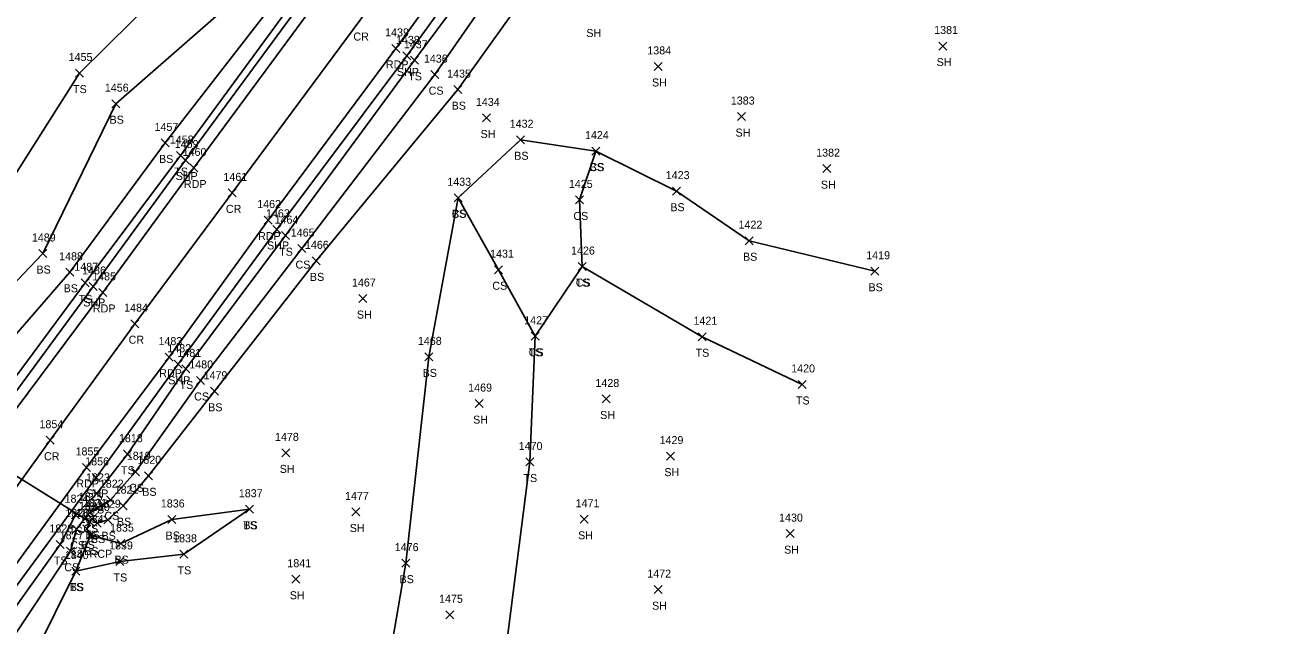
# Model space of a CAD drawing. Extents: x 1520648 to 1523413, y 732854 to 735518.
# Drawn here: x 1522390.5 to 1522704.9, y 734102.2 to 734252.2 of the extents above; entities that cross this region are included whole.
import ezdxf

# ---------------------------------------------------------------- set-up
doc = ezdxf.new("R2010")
doc.units = 0
for name, color, linetype in [('D_A', 7, 'Continuous'), ('D_C', 7, 'Continuous'), ('D_I', 7, 'Continuous'), ('D_TIC', 7, 'Continuous'), ('DCP', 7, 'Continuous'), ('L_A', 7, 'Continuous'), ('L_I', 7, 'Continuous'), ('L_TIC', 7, 'Continuous'), ('LELB', 7, 'Continuous'), ('P_A', 7, 'Continuous'), ('P_I', 7, 'Continuous'), ('P_TIC', 7, 'Continuous'), ('PET', 7, 'Continuous'), ('PRC', 7, 'Continuous'), ('PSP', 7, 'Continuous')]:
    doc.layers.add(name, color=color, linetype=linetype)

msp = doc.modelspace()

# ---------------------------------------------------------------- linework, layer by layer
at = {"layer": 'D_TIC'}
for points in [[(1522405.62, 734127.21), (1522407.62, 734129.21)], [(1522407.62, 734127.21), (1522405.62, 734129.21)]]:
    msp.add_lwpolyline(points, dxfattribs=at)
at = {"layer": 'DCP'}
msp.add_lwpolyline([(1522367.37, 734152.56), (1522406.62, 734128.21)], dxfattribs=at)
at = {"layer": 'L_TIC'}
for points in [[(1522618.68, 734245.97), (1522620.68, 734247.97)], [(1522620.68, 734245.97), (1522618.68, 734247.97)], [(1522486.75, 734242.4), (1522488.75, 734244.4)], [(1522488.75, 734242.4), (1522486.75, 734244.4)], [(1522547.57, 734240.87), (1522549.57, 734242.87)], [(1522549.57, 734240.87), (1522547.57, 734242.87)], [(1522403.02, 734239.22), (1522405.02, 734241.22)], [(1522405.02, 734239.22), (1522403.02, 734241.22)], [(1522491.81, 734238.83), (1522493.81, 734240.83)], [(1522493.81, 734238.83), (1522491.81, 734240.83)], [(1522497.57, 734235.08), (1522499.57, 734237.08)], [(1522499.57, 734235.08), (1522497.57, 734237.08)], [(1522412.12, 734231.57), (1522414.12, 734233.57)], [(1522414.12, 734231.57), (1522412.12, 734233.57)], [(1522504.75, 734228.01), (1522506.75, 734230.01)], [(1522506.75, 734228.01), (1522504.75, 734230.01)], [(1522568.44, 734228.36), (1522570.44, 734230.36)], [(1522570.44, 734228.36), (1522568.44, 734230.36)], [(1522424.47, 734221.78), (1522426.47, 734223.78)], [(1522426.47, 734221.78), (1522424.47, 734223.78)], [(1522513.21, 734222.57), (1522515.21, 734224.57)], [(1522515.21, 734222.57), (1522513.21, 734224.57)], [(1522428.3, 734218.62), (1522430.3, 734220.62)], [(1522430.3, 734218.62), (1522428.3, 734220.62)], [(1522532.01, 734219.74), (1522534.01, 734221.74)], [(1522534.01, 734219.74), (1522532.01, 734221.74)], [(1522532.01, 734219.74), (1522534.01, 734221.74)], [(1522534.01, 734219.74), (1522532.01, 734221.74)], [(1522589.77, 734215.36), (1522591.77, 734217.36)], [(1522591.77, 734215.36), (1522589.77, 734217.36)], [(1522552.2, 734209.74), (1522554.2, 734211.74)], [(1522554.2, 734209.74), (1522552.2, 734211.74)], [(1522497.61, 734208.08), (1522499.61, 734210.08)], [(1522499.61, 734208.08), (1522497.61, 734210.08)], [(1522497.61, 734208.08), (1522499.61, 734210.08)], [(1522499.61, 734208.08), (1522497.61, 734210.08)], [(1522527.98, 734207.55), (1522529.98, 734209.55)], [(1522529.98, 734207.55), (1522527.98, 734209.55)], [(1522454.5, 734198.63), (1522456.5, 734200.63)], [(1522456.5, 734198.63), (1522454.5, 734200.63)], [(1522570.36, 734197.37), (1522572.36, 734199.37)], [(1522572.36, 734197.37), (1522570.36, 734199.37)], [(1522393.84, 734194.17), (1522395.84, 734196.17)], [(1522395.84, 734194.17), (1522393.84, 734196.17)], [(1522458.56, 734195.4), (1522460.56, 734197.4)], [(1522460.56, 734195.4), (1522458.56, 734197.4)], [(1522462.16, 734192.34), (1522464.16, 734194.34)], [(1522464.16, 734192.34), (1522462.16, 734194.34)], [(1522507.73, 734190.13), (1522509.73, 734192.13)], [(1522509.73, 734190.13), (1522507.73, 734192.13)], [(1522528.58, 734190.91), (1522530.58, 734192.91)], [(1522530.58, 734190.91), (1522528.58, 734192.91)], [(1522528.58, 734190.91), (1522530.58, 734192.91)], [(1522530.58, 734190.91), (1522528.58, 734192.91)], [(1522400.64, 734189.49), (1522402.64, 734191.49)], [(1522402.64, 734189.49), (1522400.64, 734191.49)], [(1522404.44, 734186.85), (1522406.44, 734188.85)], [(1522406.44, 734186.85), (1522404.44, 734188.85)], [(1522601.7, 734189.74), (1522603.7, 734191.74)], [(1522603.7, 734189.74), (1522601.7, 734191.74)], [(1522473.84, 734182.93), (1522475.84, 734184.93)], [(1522475.84, 734182.93), (1522473.84, 734184.93)], [(1522516.84, 734173.51), (1522518.84, 734175.51)], [(1522518.84, 734173.51), (1522516.84, 734175.51)], [(1522516.84, 734173.51), (1522518.84, 734175.51)], [(1522518.84, 734173.51), (1522516.84, 734175.51)], [(1522558.55, 734173.4), (1522560.55, 734175.4)], [(1522560.55, 734173.4), (1522558.55, 734175.4)], [(1522490.31, 734168.37), (1522492.31, 734170.37)], [(1522492.31, 734168.37), (1522490.31, 734170.37)], [(1522429.63, 734165.37), (1522431.63, 734167.37)], [(1522431.63, 734165.37), (1522429.63, 734167.37)], [(1522433.24, 734162.49), (1522435.24, 734164.49)], [(1522435.24, 734162.49), (1522433.24, 734164.49)], [(1522436.74, 734159.79), (1522438.74, 734161.79)], [(1522438.74, 734159.79), (1522436.74, 734161.79)], [(1522583.61, 734161.49), (1522585.61, 734163.49)], [(1522585.61, 734161.49), (1522583.61, 734163.49)], [(1522502.89, 734156.71), (1522504.89, 734158.71)], [(1522504.89, 734156.71), (1522502.89, 734158.71)], [(1522534.62, 734157.86), (1522536.62, 734159.86)], [(1522536.62, 734157.86), (1522534.62, 734159.86)], [(1522415.02, 734144.08), (1522417.02, 734146.08)], [(1522417.02, 734144.08), (1522415.02, 734146.08)], [(1522454.56, 734144.41), (1522456.56, 734146.41)], [(1522456.56, 734144.41), (1522454.56, 734146.41)], [(1522550.65, 734143.6), (1522552.65, 734145.6)], [(1522552.65, 734143.6), (1522550.65, 734145.6)], [(1522416.99, 734139.69), (1522418.99, 734141.69)], [(1522418.99, 734139.69), (1522416.99, 734141.69)], [(1522515.54, 734142.14), (1522517.54, 734144.14)], [(1522517.54, 734142.14), (1522515.54, 734144.14)], [(1522420.27, 734138.69), (1522422.27, 734140.69)], [(1522422.27, 734138.69), (1522420.27, 734140.69)], [(1522407.37, 734134.28), (1522409.37, 734136.28)], [(1522409.37, 734134.28), (1522407.37, 734136.28)], [(1522410.81, 734132.72), (1522412.81, 734134.72)], [(1522412.81, 734132.72), (1522410.81, 734134.72)], [(1522413.94, 734131.23), (1522415.94, 734133.23)], [(1522415.94, 734131.23), (1522413.94, 734133.23)], [(1522445.53, 734130.34), (1522447.53, 734132.34)], [(1522447.53, 734130.34), (1522445.53, 734132.34)], [(1522445.53, 734130.34), (1522447.53, 734132.34)], [(1522447.53, 734130.34), (1522445.53, 734132.34)], [(1522402.01, 734128.97), (1522404.01, 734130.97)], [(1522404.01, 734128.97), (1522402.01, 734130.97)], [(1522405.56, 734129.49), (1522407.56, 734131.49)], [(1522407.56, 734129.49), (1522405.56, 734131.49)], [(1522406.08, 734127.93), (1522408.08, 734129.93)], [(1522408.08, 734127.93), (1522406.08, 734129.93)], [(1522410.1, 734127.72), (1522412.1, 734129.72)], [(1522412.1, 734127.72), (1522410.1, 734129.72)], [(1522426.11, 734127.78), (1522428.11, 734129.78)], [(1522428.11, 734127.78), (1522426.11, 734129.78)], [(1522472.06, 734129.66), (1522474.06, 734131.66)], [(1522474.06, 734129.66), (1522472.06, 734131.66)], [(1522529.11, 734127.84), (1522531.11, 734129.84)], [(1522531.11, 734127.84), (1522529.11, 734129.84)], [(1522402.25, 734125.38), (1522404.25, 734127.38)], [(1522404.25, 734125.38), (1522402.25, 734127.38)], [(1522404.88, 734125.45), (1522406.88, 734127.45)], [(1522406.88, 734125.45), (1522404.88, 734127.45)], [(1522405.78, 734123.9), (1522407.78, 734125.9)], [(1522407.78, 734123.9), (1522405.78, 734125.9)], [(1522405.78, 734123.9), (1522407.78, 734125.9)], [(1522407.78, 734123.9), (1522405.78, 734125.9)], [(1522407.44, 734126.9), (1522409.44, 734128.9)], [(1522409.44, 734126.9), (1522407.44, 734128.9)], [(1522580.58, 734124.25), (1522582.58, 734126.25)], [(1522582.58, 734124.25), (1522580.58, 734126.25)], [(1522398.21, 734121.54), (1522400.21, 734123.54)], [(1522400.21, 734121.54), (1522398.21, 734123.54)], [(1522413.36, 734121.75), (1522415.36, 734123.75)], [(1522415.36, 734121.75), (1522413.36, 734123.75)], [(1522400.8, 734119.85), (1522402.8, 734121.85)], [(1522402.8, 734119.85), (1522400.8, 734121.85)], [(1522429.11, 734119.09), (1522431.11, 734121.09)], [(1522431.11, 734119.09), (1522429.11, 734121.09)], [(1522402.15, 734114.91), (1522404.15, 734116.91)], [(1522404.15, 734114.91), (1522402.15, 734116.91)], [(1522402.15, 734114.91), (1522404.15, 734116.91)], [(1522404.15, 734114.91), (1522402.15, 734116.91)], [(1522413.13, 734117.31), (1522415.13, 734119.31)], [(1522415.13, 734117.31), (1522413.13, 734119.31)], [(1522484.55, 734116.88), (1522486.55, 734118.88)], [(1522486.55, 734116.88), (1522484.55, 734118.88)], [(1522457.09, 734112.87), (1522459.09, 734114.87)], [(1522459.09, 734112.87), (1522457.09, 734114.87)], [(1522547.58, 734110.27), (1522549.58, 734112.27)], [(1522549.58, 734110.27), (1522547.58, 734112.27)], [(1522495.55, 734103.98), (1522497.55, 734105.98)], [(1522497.55, 734103.98), (1522495.55, 734105.98)]]:
    msp.add_lwpolyline(points, dxfattribs=at)
at = {"layer": 'LELB'}
for points in [[(1522785.93, 734645.15), (1522756.48, 734606.7), (1522726.02, 734567.19), (1522697.44, 734525.1), (1522656.53, 734469.54), (1522622.12, 734421.12), (1522590.47, 734378.52), (1522566.34, 734346.2), (1522539.5, 734310.16), (1522511.43, 734266.75), (1522492.81, 734239.83), (1522459.56, 734196.4), (1522434.24, 734163.49), (1522417.99, 734140.69), (1522411.81, 734133.72), (1522406.56, 734130.49), (1522403.25, 734126.38), (1522401.8, 734120.85), (1522386.75, 734098.22)], [(1522693.92, 734527.21), (1522653.61, 734471.8), (1522618.94, 734423.11), (1522588.19, 734381.05), (1522564.23, 734347.84), (1522537.14, 734311.9), (1522506.92, 734269.19), (1522487.75, 734243.4), (1522455.5, 734199.63), (1522430.63, 734166.37), (1522416.02, 734145.08), (1522408.37, 734135.28), (1522403.01, 734129.97), (1522399.21, 734122.54), (1522383.71, 734100.99)], [(1522704.24, 734521.86), (1522660.18, 734466.65), (1522629.05, 734416.78), (1522593.47, 734376.61), (1522578.57, 734355.18), (1522577.23, 734351.34), (1522574.67, 734346.79), (1522570.51, 734341.94), (1522542.46, 734307.95), (1522517.77, 734263), (1522498.57, 734236.08), (1522463.16, 734193.34), (1522437.74, 734160.79), (1522421.27, 734139.69), (1522414.94, 734132.23), (1522411.1, 734128.72), (1522408.44, 734127.9), (1522407.08, 734128.93), (1522405.88, 734126.45), (1522406.78, 734124.9), (1522403.15, 734115.91), (1522392.7, 734094.89), (1522365.31, 734053.94)], [(1522395.09, 734350.53), (1522415.25, 734331.59), (1522444.22, 734311.43), (1522451.41, 734298.65), (1522468.17, 734280.37), (1522463.01, 734272.97), (1522457.88, 734264.64), (1522425.47, 734222.78), (1522401.64, 734190.49), (1522371.91, 734156.31), (1522371.61, 734153.22)], [(1522384.49, 734338.49), (1522408.87, 734322.63), (1522444.22, 734311.43), (1522437.11, 734272.85), (1522404.02, 734240.22), (1522381.49, 734204.71), (1522358.63, 734188.03), (1522348.69, 734185.07), (1522337.79, 734178.25), (1522344.61, 734158.44), (1522355.97, 734160.39), (1522362.76, 734161.47), (1522371.91, 734156.31), (1522376.81, 734157.78), (1522380.78, 734154.69)], [(1522457.97, 734316.51), (1522465.36, 734303.49), (1522470.91, 734292.36), (1522471.73, 734284.06), (1522466.06, 734271.74), (1522460.87, 734262.7), (1522429.3, 734219.62), (1522405.44, 734187.85), (1522380.78, 734154.69), (1522358.58, 734123.49), (1522334.87, 734095.05), (1522309.58, 734064.85), (1522289.9, 734038.9), (1522256.58, 733995.71), (1522247.93, 733981.24), (1522246.39, 733977.74)], [(1522468.17, 734280.37), (1522452.7, 734267.12), (1522413.12, 734232.57), (1522394.84, 734195.17), (1522362.76, 734161.47)], [(1522602.7, 734190.74), (1522571.36, 734198.37), (1522553.2, 734210.74), (1522533.01, 734220.74), (1522514.21, 734223.57), (1522498.61, 734209.08), (1522491.31, 734169.37), (1522485.55, 734117.88), (1522480.33, 734087.35), (1522469.38, 734038.25), (1522443.9, 733998.64), (1522419.91, 733961.31), (1522415.53, 733936.63), (1522421.2, 733921.09)], [(1522533.01, 734220.74), (1522528.98, 734208.55), (1522529.58, 734191.91)], [(1522517.84, 734174.51), (1522508.73, 734191.13), (1522498.61, 734209.08)], [(1522584.61, 734162.49), (1522559.55, 734174.4), (1522529.58, 734191.91), (1522517.84, 734174.51), (1522516.54, 734143.14), (1522509.73, 734089.66), (1522511.25, 734056.33), (1522492.52, 734020.47), (1522469.44, 733975.57), (1522449.61, 733947.95)], [(1522446.53, 734131.34), (1522430.11, 734120.09), (1522414.13, 734118.31), (1522403.15, 734115.91)], [(1522406.78, 734124.9), (1522414.36, 734122.75), (1522427.11, 734128.78), (1522446.53, 734131.34)]]:
    msp.add_lwpolyline(points, dxfattribs=at)
at = {"layer": 'P_TIC'}
for points in [[(1522482.1, 734245.38), (1522484.1, 734247.38)], [(1522484.1, 734245.38), (1522482.1, 734247.38)], [(1522484.78, 734243.5), (1522486.78, 734245.5)], [(1522486.78, 734243.5), (1522484.78, 734245.5)], [(1522429.53, 734217.51), (1522431.53, 734219.51)], [(1522431.53, 734217.51), (1522429.53, 734219.51)], [(1522431.63, 734215.53), (1522433.63, 734217.53)], [(1522433.63, 734215.53), (1522431.63, 734217.53)], [(1522441.17, 734209.31), (1522443.17, 734211.31)], [(1522443.17, 734209.31), (1522441.17, 734211.31)], [(1522450.17, 734202.52), (1522452.17, 734204.52)], [(1522452.17, 734202.52), (1522450.17, 734204.52)], [(1522452.37, 734200.19), (1522454.37, 734202.19)], [(1522454.37, 734200.19), (1522452.37, 734202.19)], [(1522406.44, 734185.96), (1522408.44, 734187.96)], [(1522408.44, 734185.96), (1522406.44, 734187.96)], [(1522408.89, 734184.46), (1522410.89, 734186.46)], [(1522410.89, 734184.46), (1522408.89, 734186.46)], [(1522416.88, 734176.66), (1522418.88, 734178.66)], [(1522418.88, 734176.66), (1522416.88, 734178.66)], [(1522425.47, 734168.3), (1522427.47, 734170.3)], [(1522427.47, 734168.3), (1522425.47, 734170.3)], [(1522427.68, 734166.53), (1522429.68, 734168.53)], [(1522429.68, 734166.53), (1522427.68, 734168.53)], [(1522395.73, 734147.57), (1522397.73, 734149.57)], [(1522397.73, 734147.57), (1522395.73, 734149.57)], [(1522404.75, 734140.77), (1522406.75, 734142.77)], [(1522406.75, 734140.77), (1522404.75, 734142.77)], [(1522407.2, 734138.28), (1522409.2, 734140.28)], [(1522409.2, 734138.28), (1522407.2, 734140.28)]]:
    msp.add_lwpolyline(points, dxfattribs=at)
at = {"layer": 'PET'}
for points in [[(1522868.59, 734820.36), (1522840.66, 734781.56), (1522808.05, 734736.15), (1522781.8, 734699.35), (1522756.93, 734664.88), (1522728.19, 734624.99), (1522698.77, 734583.51), (1522668.99, 734541.94), (1522630.29, 734488.99), (1522594.44, 734439.3), (1522567.25, 734402.07), (1522538.71, 734362.22), (1522514.31, 734328.64), (1522482.43, 734284.06), (1522464.74, 734260.16), (1522432.63, 734216.53), (1522409.89, 734185.46), (1522384.8, 734151.86)], [(1522887.76, 734807.39), (1522860.85, 734769.52), (1522801.36, 734686.8), (1522776.05, 734652.1), (1522748.04, 734612.12), (1522718.66, 734571.41), (1522688.63, 734530.01), (1522649.15, 734475.23), (1522613.31, 734425.7), (1522584.29, 734385.79), (1522558.85, 734350.63), (1522533.2, 734315.44), (1522501.29, 734271.61), (1522483.1, 734246.38), (1522451.17, 734203.52), (1522426.47, 734169.3), (1522405.75, 734141.77), (1522378.63, 734104.64)]]:
    msp.add_lwpolyline(points, dxfattribs=at)
at = {"layer": 'PRC'}
msp.add_lwpolyline([(1522878.51, 734813.79), (1522851.06, 734774.87), (1522817.97, 734729.86), (1522791.97, 734693.14), (1522766.66, 734657.61), (1522738.9, 734618.17), (1522708.24, 734576.9), (1522678.84, 734535.68), (1522640.14, 734482.21), (1522604.52, 734432.45), (1522576.44, 734394.44), (1522548.3, 734356.14), (1522523.72, 734322.36), (1522491.79, 734277.99), (1522474.03, 734253.33), (1522442.17, 734210.31), (1522417.88, 734177.66), (1522396.73, 734148.57), (1522369.92, 734111.45)], dxfattribs=at)
at = {"layer": 'PSP'}
for points in [[(1522864.28, 734823.23), (1522837.44, 734783.06), (1522805.48, 734737.59), (1522779.45, 734700.71), (1522754.96, 734666.26), (1522726.27, 734626.48), (1522696.55, 734585.36), (1522666.29, 734543.52), (1522637.15, 734503.6), (1522619.94, 734478.45), (1522592.3, 734440.3), (1522565.28, 734403.71), (1522536.3, 734363.73), (1522513.91, 734332.75), (1522468.75, 734270.57), (1522462.45, 734261.84), (1522430.53, 734218.51), (1522407.44, 734186.96), (1522382.7, 734153.4)], [(1522891.61, 734804.38), (1522863.83, 734767.51), (1522842.38, 734738.09), (1522825.83, 734714.72), (1522803.35, 734683.95), (1522778.9, 734649.79), (1522750.84, 734610.4), (1522721.18, 734569.96), (1522691.62, 734528.08), (1522651.91, 734473.19), (1522616.71, 734423.72), (1522586.83, 734383.52), (1522561.92, 734348.87), (1522535.83, 734313.09), (1522504.54, 734270.39), (1522485.78, 734244.5), (1522453.37, 734201.19), (1522428.68, 734167.53), (1522408.2, 734139.28), (1522381.04, 734102.47)]]:
    msp.add_lwpolyline(points, dxfattribs=at)

# ---------------------------------------------------------------- texts
at = {"layer": 'D_A'}
msp.add_text('P', height=2, dxfattribs=at).set_placement((1522406, 734123.21))
at = {"layer": 'D_C'}
msp.add_text('18" RCP', height=2, dxfattribs=at).set_placement((1522401.9, 734119.21))
at = {"layer": 'D_I'}
msp.add_text('1833', height=2, dxfattribs=at).set_placement((1522403.93, 734131.21))
at = {"layer": 'L_A'}
for s, p in [('SH', (1522530.65, 734249.21)), ('SH', (1522618.17, 734241.97)), ('TS', (1522486.16, 734238.4)), ('TS', (1522402.43, 734235.22)), ('CS', (1522491.26, 734234.83)), ('SH', (1522547.06, 734236.87)), ('BS', (1522497.01, 734231.08)), ('BS', (1522411.56, 734227.57)), ('SH', (1522504.24, 734224.01)), ('SH', (1522567.93, 734224.36)), ('BS', (1522512.65, 734218.57)), ('BS', (1522423.91, 734217.78)), ('CS', (1522531.46, 734215.74)), ('BS', (1522531.46, 734215.74)), ('TS', (1522427.71, 734214.62)), ('SH', (1522589.25, 734211.36)), ('BS', (1522551.64, 734205.74)), ('CS', (1522497.05, 734204.08)), ('BS', (1522497.05, 734204.08)), ('CS', (1522527.42, 734203.55)), ('TS', (1522453.91, 734194.63)), ('BS', (1522569.8, 734193.37)), ('BS', (1522393.28, 734190.17)), ('CS', (1522458, 734191.4)), ('BS', (1522461.6, 734188.34)), ('TS', (1522527.99, 734186.91)), ('CS', (1522528.02, 734186.91)), ('BS', (1522400.08, 734185.49)), ('CS', (1522507.17, 734186.13)), ('BS', (1522601.14, 734185.74)), ('TS', (1522403.84, 734182.85)), ('SH', (1522473.33, 734178.93)), ('TS', (1522516.25, 734169.51)), ('CS', (1522516.28, 734169.51)), ('TS', (1522557.95, 734169.4)), ('BS', (1522489.76, 734164.37)), ('TS', (1522429.04, 734161.37)), ('CS', (1522432.68, 734158.49)), ('BS', (1522436.18, 734155.79)), ('TS', (1522583.02, 734157.49)), ('SH', (1522502.38, 734152.71)), ('SH', (1522534.11, 734153.86)), ('TS', (1522414.42, 734140.08)), ('SH', (1522454.05, 734140.41)), ('SH', (1522550.14, 734139.6)), ('TS', (1522514.95, 734138.14)), ('CS', (1522416.43, 734135.69)), ('BS', (1522419.72, 734134.69)), ('TS', (1522406.78, 734130.28)), ('CS', (1522410.25, 734128.72)), ('BS', (1522413.39, 734127.23)), ('TS', (1522401.42, 734124.97)), ('CS', (1522405, 734125.49)), ('BS', (1522405.53, 734123.93)), ('TS', (1522444.94, 734126.34)), ('BS', (1522444.97, 734126.34)), ('SH', (1522471.55, 734125.66)), ('SH', (1522528.6, 734123.84)), ('CS', (1522401.69, 734121.38)), ('BS', (1522404.33, 734121.45)), ('BS', (1522406.88, 734122.9)), ('BS', (1522409.54, 734123.72)), ('BS', (1522425.55, 734123.78)), ('TS', (1522397.62, 734117.54)), ('BS', (1522405.22, 734119.9)), ('BS', (1522405.22, 734119.9)), ('BS', (1522412.8, 734117.75)), ('SH', (1522580.07, 734120.25)), ('CS', (1522400.24, 734115.85)), ('TS', (1522428.52, 734115.09)), ('TS', (1522412.54, 734113.31)), ('BS', (1522483.99, 734112.88)), ('TS', (1522401.56, 734110.91)), ('BS', (1522401.59, 734110.91)), ('SH', (1522456.57, 734108.87)), ('SH', (1522547.07, 734106.27))]:
    msp.add_text(s, height=2, dxfattribs=at).set_placement(p)
at = {"layer": 'L_I'}
for s, p in [('1381', (1522617.55, 734249.97)), ('1437', (1522485.06, 734246.4)), ('1384', (1522545.88, 734244.87)), ('1455', (1522401.32, 734243.22)), ('1436', (1522490.07, 734242.83)), ('1435', (1522495.88, 734239.08)), ('1456', (1522410.37, 734235.57)), ('1434', (1522503.06, 734232.01)), ('1383', (1522566.75, 734232.36)), ('1457', (1522422.78, 734225.78)), ('1432', (1522511.51, 734226.57)), ('1458', (1522426.6, 734222.62)), ('1424', (1522530.32, 734223.74)), ('1424', (1522530.32, 734223.74)), ('1382', (1522588.07, 734219.36)), ('1433', (1522495.92, 734212.08)), ('1433', (1522495.92, 734212.08)), ('1423', (1522550.5, 734213.74)), ('1425', (1522526.29, 734211.55)), ('1464', (1522452.76, 734202.63)), ('1465', (1522456.82, 734199.4)), ('1422', (1522568.67, 734201.37)), ('1489', (1522392.14, 734198.17)), ('1466', (1522460.36, 734196.34)), ('1488', (1522398.95, 734193.49)), ('1431', (1522506.61, 734194.13)), ('1426', (1522526.83, 734194.91)), ('1426', (1522526.83, 734194.91)), ('1419', (1522600.57, 734193.74)), ('1487', (1522402.74, 734190.85)), ('1467', (1522472.1, 734186.93)), ('1427', (1522515.14, 734177.51)), ('1427', (1522515.14, 734177.51)), ('1421', (1522557.42, 734177.4)), ('1468', (1522488.57, 734172.37)), ('1481', (1522428.5, 734169.37)), ('1480', (1522431.46, 734166.49)), ('1420', (1522581.83, 734165.49)), ('1479', (1522435.04, 734163.79)), ('1428', (1522532.93, 734161.86)), ('1469', (1522501.14, 734160.71)), ('1818', (1522413.89, 734148.08)), ('1478', (1522452.87, 734148.41)), ('1470', (1522513.76, 734146.14)), ('1429', (1522548.95, 734147.6)), ('1819', (1522415.86, 734143.69)), ('1820', (1522418.5, 734142.69)), ('1823', (1522405.68, 734138.28)), ('1822', (1522409.11, 734136.72)), ('1825', (1522403.86, 734133.49)), ('1821', (1522412.82, 734135.23)), ('1837', (1522443.84, 734134.34)), ('1837', (1522443.84, 734134.34)), ('1477', (1522470.37, 734133.66)), ('1824', (1522400.31, 734132.97)), ('1831', (1522404.96, 734131.93)), ('1830', (1522405.66, 734130.9)), ('1829', (1522408.4, 734131.72)), ('1836', (1522424.36, 734131.78)), ('1471', (1522527.98, 734131.84)), ('1826', (1522400.5, 734129.38)), ('1832', (1522403.19, 734129.45)), ('1834', (1522404.09, 734127.9)), ('1834', (1522404.09, 734127.9)), ('1430', (1522578.8, 734128.25)), ('1828', (1522396.52, 734125.54)), ('1827', (1522399.1, 734123.85)), ('1835', (1522411.67, 734125.75)), ('1839', (1522411.43, 734121.31)), ('1838', (1522427.42, 734123.09)), ('1476', (1522482.8, 734120.88)), ('1840', (1522400.37, 734118.91)), ('1840', (1522400.37, 734118.91)), ('1841', (1522455.96, 734116.87)), ('1472', (1522545.88, 734114.27)), ('1475', (1522493.86, 734107.98))]:
    msp.add_text(s, height=2, dxfattribs=at).set_placement(p)
at = {"layer": 'P_A'}
for s, p in [('CR', (1522472.47, 734248.33)), ('RDP', (1522480.58, 734241.38)), ('SHP', (1522483.32, 734239.5)), ('SHP', (1522428.06, 734213.51)), ('RDP', (1522430.12, 734211.53)), ('CR', (1522440.61, 734205.31)), ('RDP', (1522448.66, 734198.52)), ('SHP', (1522450.9, 734196.19)), ('SHP', (1522404.97, 734181.96)), ('RDP', (1522407.38, 734180.46)), ('CR', (1522416.31, 734172.66)), ('RDP', (1522423.96, 734164.3)), ('SHP', (1522426.21, 734162.53)), ('CR', (1522395.17, 734143.57)), ('RDP', (1522403.24, 734136.77)), ('SHP', (1522405.74, 734134.28))]:
    msp.add_text(s, height=2, dxfattribs=at).set_placement(p)
at = {"layer": 'P_I'}
for s, p in [('1439', (1522480.39, 734249.38)), ('1438', (1522483.09, 734247.5)), ('1459', (1522427.83, 734221.51)), ('1460', (1522429.8, 734219.53)), ('1461', (1522440, 734213.31)), ('1462', (1522448.43, 734206.52)), ('1463', (1522450.63, 734204.19)), ('1486', (1522404.69, 734189.96)), ('1485', (1522407.2, 734188.46)), ('1484', (1522415.19, 734180.66)), ('1483', (1522423.77, 734172.3)), ('1482', (1522425.98, 734170.53)), ('1854', (1522394.04, 734151.57)), ('1855', (1522403.05, 734144.77)), ('1856', (1522405.46, 734142.28))]:
    msp.add_text(s, height=2, dxfattribs=at).set_placement(p)

doc.saveas('drawing.dxf')
